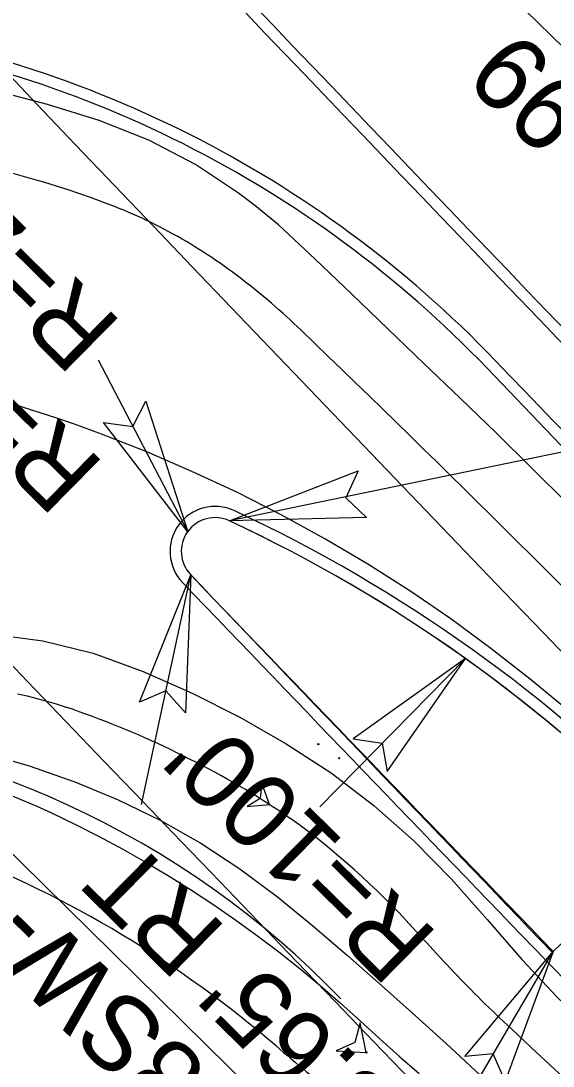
# Model space of a CAD drawing. Extents: x 1262642 to 1268358, y 767825 to 773481.
# Drawn here: x 1266795.4 to 1266830.8, y 772090.6 to 772160.2 of the extents above; entities that cross this region are included whole.
import ezdxf

# ---------------------------------------------------------------- set-up
doc = ezdxf.new("R2010")
doc.units = 0
for name, color, linetype in [('Prop Conc 5in Monolithic Keyed In Island', 7, 'Continuous'), ('Prop Dimension', 7, 'Continuous'), ('Prop Dimension Text', 7, 'Continuous'), ('Prop EOT', 7, 'Continuous'), ('Prop Horizontal Alignment', 7, 'Continuous'), ('Prop Lane Lines', 7, 'Continuous'), ('Prop Shade Light', 7, 'Continuous'), ('Prop Shade Medium', 7, 'Continuous'), ('Prop Terminator CELL', 7, 'Continuous'), ('Scratch_Level_3', 7, 'Continuous')]:
    doc.layers.add(name, color=color, linetype=linetype)

msp = doc.modelspace()

# ---------------------------------------------------------------- linework, layer by layer
at = {"layer": 'Prop Conc 5in Monolithic Keyed In Island'}
msp.add_line((1266830.753, 772098.262), (1266838.671, 772105.898), dxfattribs=at)
for centre, radius, start, end in [((1275047.307, 780021.225), 11385.75, 223.6505027, 224.2564693), ((1266772.773, 772085.698), 75, 43.80193, 82.74583), ((1275047.307, 780021.225), 11389.75, 223.8019285, 224.2564698), ((1266808.274, 772124.892), 2.25, 64.96498, 223.78327), ((1266767.185, 772036.948), 99.319, 43.95043, 64.95755), ((1275064.49, 780003.257), 11414.25, 223.6584765, 223.8330599)]:
    msp.add_arc(centre, radius, start, end, dxfattribs=at)
at = {"layer": 'Prop Dimension Text'}
for p, q in [((1266851.227, 772138.936), (1266824.646, 772165.127)), ((1266800.488, 772137.651), (1266806.45, 772126.196)), ((1266820.023, 772079.893), (1266772.475, 772126.743)), ((1266815.248, 772107.896), (1266824.925, 772117.759))]:
    msp.add_line(p, q, dxfattribs=at)
for points in [[(1266948.393, 772155.686), (1266809.22, 772126.931)], [(1266803.368, 772108.057), (1266806.649, 772123.335)], [(1266822.822, 772084.668), (1266830.753, 772098.262)]]:
    msp.add_lwpolyline(points, dxfattribs=at)
at = {"layer": 'Prop EOT'}
for centre, radius, start, end in [((1275047.307, 780021.225), 11385, 223.6505027, 224.2564693), ((1266772.773, 772085.698), 74.25, 43.80193, 82.74583), ((1275047.307, 780021.225), 11390.5, 223.8019285, 224.2564693), ((1266808.274, 772124.892), 3, 64.96497, 223.78327), ((1266767.226, 772037.005), 100, 43.95786, 64.96497), ((1275047.307, 780021.225), 11415, 223.7832702, 223.9578537), ((1275047.307, 780021.225), 11415, 223.9578709, 224.2520264), ((1266699.67, 771910.536), 200, 44.17518, 66.65746)]:
    msp.add_arc(centre, radius, start, end, dxfattribs=at)
at = {"layer": 'Prop Horizontal Alignment'}
msp.add_arc((1275047.307, 780021.225), 11400, 222.9935866, 225.4043192, dxfattribs=at)
at = {"layer": 'Prop Lane Lines'}
for centre, radius, start, end in [((1275047.307, 780021.225), 11427, 222.9935866, 225.3637298), ((1266773.416, 772053.492), 60, 43.9174, 86.78605)]:
    msp.add_arc(centre, radius, start, end, dxfattribs=at)
at = {"layer": 'Prop Shade Light'}
msp.add_arc((1266699.67, 771910.536), 200, 44.17518, 66.65746, dxfattribs=at)
at = {"layer": 'Prop Shade Medium'}
msp.add_line((1266830.753, 772098.262), (1266838.671, 772105.898), dxfattribs=at)
for centre, radius, start, end in [((1275047.307, 780021.225), 11385.75, 223.6505027, 224.2564693), ((1266772.773, 772085.698), 75, 43.80193, 82.74583), ((1275047.307, 780021.225), 11389.75, 223.8019285, 224.2564698), ((1266808.274, 772124.892), 2.25, 64.96498, 223.78327), ((1266767.226, 772037.005), 99.25, 43.95785, 64.96498), ((1275047.307, 780021.225), 11414.25, 223.7832702, 223.9578537)]:
    msp.add_arc(centre, radius, start, end, dxfattribs=at)
at = {"layer": 'Prop Terminator CELL'}
for points in [[(1266803.67, 772134.895), (1266806.45, 772126.196), (1266800.852, 772133.485), (1266802.803, 772133.204)], [(1266818.35, 772127.15), (1266809.22, 772126.931), (1266817.79, 772130.25), (1266816.971, 772128.458)], [(1266803.243, 772114.862), (1266806.649, 772123.335), (1266806.312, 772114.151), (1266804.989, 772115.612)], [(1266819.728, 772110.249), (1266824.925, 772117.759), (1266817.445, 772112.42), (1266819.392, 772112.12)], [(1266824.879, 772091.27), (1266830.753, 772098.262), (1266827.574, 772089.639), (1266826.772, 772091.439)]]:
    msp.add_lwpolyline(points, close=True, dxfattribs=at)
at = {"layer": 'Scratch_Level_3'}
for points in [[(1266810.921, 772147.927), (1266809.834, 772148.75), (1266806.958, 772150.648), (1266803.86, 772152.275), (1266800.55, 772153.584), (1266797.116, 772154.652), (1266793.633, 772155.548), (1266790.109, 772156.268), (1266786.554, 772156.812), (1266782.975, 772157.177), (1266779.383, 772157.363), (1266775.786, 772157.37), (1266772.199, 772157.207), (1266768.664, 772157.055), (1266765.183, 772157.013), (1266761.734, 772157.034), (1266758.285, 772156.973), (1266754.839, 772156.827), (1266751.398, 772156.596), (1266747.963, 772156.28), (1266747.277, 772156.207)], [(1266813.987, 772139.615), (1266813.747, 772139.845), (1266813.505, 772140.074), (1266813.261, 772140.302), (1266813.016, 772140.528), (1266812.769, 772140.752), (1266812.521, 772140.975), (1266812.271, 772141.195), (1266812.02, 772141.414), (1266811.767, 772141.631), (1266811.512, 772141.846), (1266811.256, 772142.059), (1266810.998, 772142.27), (1266810.738, 772142.48), (1266810.477, 772142.687), (1266810.214, 772142.892), (1266809.95, 772143.095), (1266809.684, 772143.295), (1266809.416, 772143.494), (1266809.147, 772143.69), (1266808.875, 772143.884), (1266808.603, 772144.075), (1266808.328, 772144.265), (1266808.052, 772144.451), (1266807.774, 772144.636), (1266807.495, 772144.817), (1266807.214, 772144.996), (1266806.931, 772145.173), (1266806.647, 772145.347), (1266806.361, 772145.518), (1266806.073, 772145.687), (1266805.784, 772145.852), (1266805.493, 772146.015), (1266805.2, 772146.175), (1266804.906, 772146.332), (1266804.611, 772146.486), (1266804.314, 772146.637), (1266804.015, 772146.785), (1266803.715, 772146.93), (1266803.413, 772147.071), (1266803.11, 772147.21), (1266802.805, 772147.345), (1266802.499, 772147.477), (1266802.191, 772147.605), (1266801.882, 772147.73), (1266801.572, 772147.852)], [(1266831.727, 772128.067), (1266829.359, 772130.423), (1266826.98, 772132.77), (1266824.574, 772135.088), (1266822.154, 772137.394), (1266819.755, 772139.72), (1266817.35, 772142.038), (1266814.937, 772144.349), (1266812.485, 772146.631), (1266810.921, 772147.927)], [(1266798.928, 772133.354), (1266797.743, 772133.766), (1266794.83, 772134.705), (1266791.981, 772135.521), (1266789.217, 772136.214), (1266786.485, 772136.802), (1266783.759, 772137.291), (1266781.042, 772137.682), (1266778.316, 772137.981), (1266775.562, 772138.192), (1266772.773, 772138.32), (1266769.983, 772138.369), (1266767.182, 772138.349), (1266764.317, 772138.266), (1266761.377, 772138.127), (1266758.385, 772137.943), (1266755.42, 772137.732), (1266752.487, 772137.495), (1266749.6, 772137.263), (1266746.721, 772137.048), (1266746.147, 772137.008)], [(1266855.985, 772090.429), (1266853.612, 772092.905), (1266851.235, 772095.375), (1266848.861, 772097.832), (1266846.477, 772100.28), (1266844.081, 772102.715), (1266841.664, 772105.129), (1266839.218, 772107.514), (1266836.735, 772109.86), (1266836.735, 772109.86), (1266834.28, 772112.094), (1266831.78, 772114.272), (1266829.227, 772116.387), (1266826.618, 772118.431), (1266823.947, 772120.395), (1266821.215, 772122.27), (1266818.421, 772124.053), (1266815.569, 772125.74), (1266812.665, 772127.332), (1266809.716, 772128.827), (1266806.732, 772130.222), (1266803.724, 772131.515), (1266800.714, 772132.701), (1266798.928, 772133.354)], [(1266791.47, 772119.581), (1266793.471, 772119.384), (1266796.813, 772118.932), (1266800.167, 772118.113), (1266803.488, 772116.893), (1266806.745, 772115.46), (1266809.921, 772113.856), (1266813.009, 772112.086), (1266815.998, 772110.154), (1266818.826, 772107.988), (1266821.493, 772105.617), (1266824.007, 772103.084), (1266826.363, 772100.399), (1266828.673, 772097.733), (1266831.034, 772095.229), (1266833.472, 772092.899), (1266833.96, 772092.435)], [(1266795.129, 772115.42), (1266795.454, 772115.347), (1266795.778, 772115.271), (1266796.102, 772115.192), (1266796.425, 772115.109), (1266796.747, 772115.022), (1266797.068, 772114.932), (1266797.388, 772114.839), (1266797.707, 772114.741), (1266798.024, 772114.64), (1266798.34, 772114.535)], [(1266747.4, 772113.137), (1266747.688, 772113.115), (1266750.626, 772112.883), (1266753.663, 772112.644), (1266756.789, 772112.42), (1266760.041, 772112.978), (1266763.352, 772113.461), (1266766.738, 772113.677), (1266770.18, 772113.584), (1266773.653, 772113.244), (1266777.12, 772112.806), (1266780.572, 772112.261), (1266784.006, 772111.611), (1266787.419, 772110.855), (1266790.804, 772109.995), (1266794.134, 772108.899), (1266796.418, 772107.926)], [(1266790.812, 772111.995), (1266792.752, 772111.527), (1266795.913, 772110.611), (1266798.935, 772109.551), (1266801.818, 772108.362), (1266804.617, 772107.004), (1266807.322, 772105.471), (1266809.924, 772103.769), (1266812.415, 772101.91), (1266814.776, 772099.976), (1266817.068, 772098.001), (1266819.34, 772096.002), (1266821.6, 772093.982), (1266823.906, 772091.884), (1266826.269, 772089.697), (1266828.666, 772087.44), (1266829.144, 772086.984)], [(1266796.418, 772107.926), (1266797.387, 772107.482), (1266798.987, 772106.713), (1266800.57, 772105.909), (1266802.135, 772105.069), (1266803.68, 772104.195), (1266805.206, 772103.286), (1266806.71, 772102.343), (1266808.194, 772101.366), (1266809.655, 772100.357), (1266811.093, 772099.315), (1266812.507, 772098.241), (1266813.897, 772097.135), (1266815.262, 772095.999), (1266816.601, 772094.833), (1266817.914, 772093.637), (1266819.221, 772092.445), (1266820.534, 772091.282), (1266821.854, 772090.145)], [(1266811.896, 772108.05), (1266812.178, 772107.871), (1266812.457, 772107.689), (1266812.733, 772107.503), (1266813.008, 772107.314), (1266813.28, 772107.121)], [(1266821.425, 772099.846), (1266821.649, 772099.6), (1266821.873, 772099.353), (1266822.098, 772099.107), (1266822.323, 772098.861), (1266822.548, 772098.615), (1266822.773, 772098.369), (1266822.999, 772098.124), (1266823.226, 772097.88), (1266823.453, 772097.636), (1266823.681, 772097.392), (1266823.909, 772097.15), (1266824.138, 772096.907), (1266824.368, 772096.666), (1266824.598, 772096.425), (1266824.83, 772096.185), (1266825.062, 772095.946), (1266825.295, 772095.708), (1266825.529, 772095.471), (1266825.765, 772095.234), (1266826.001, 772094.999), (1266826.238, 772094.765), (1266826.477, 772094.532), (1266826.716, 772094.301), (1266826.957, 772094.07), (1266827.2, 772093.842), (1266827.443, 772093.614)], [(1266812.324, 772091.98), (1266812.577, 772091.763), (1266812.83, 772091.546), (1266813.083, 772091.329), (1266813.337, 772091.113), (1266813.591, 772090.898), (1266813.846, 772090.683), (1266814.101, 772090.468), (1266814.357, 772090.254), (1266814.614, 772090.041), (1266814.87, 772089.829), (1266815.128, 772089.617), (1266815.386, 772089.406), (1266815.645, 772089.196), (1266815.904, 772088.987)]]:
    msp.add_lwpolyline(points, dxfattribs=at)
for points in [[(1266811.896, 772108.05), (1266811.381, 772109.459), (1266811.263, 772108.452), (1266810.402, 772107.917)], [(1266818.33, 772091.544), (1266817.922, 772093.502), (1266817.572, 772092.196), (1266816.334, 772091.656)]]:
    msp.add_lwpolyline(points, close=True, dxfattribs=at)
for centre in [(1266815.137, 772112.059), (1266815.137, 772112.059), (1266816.521, 772111.13), (1266816.521, 772111.13), (1266818.33, 772091.544), (1266818.33, 772091.544)]:
    msp.add_circle(centre, 0.0417, dxfattribs=at)
for centre, radius, start, end in [((1266777.458, 772085.377), 66.967, 68.89437, 91.22346), ((1266039.974, 771332.91), 1117.975, 44.120486, 46.184771), ((1266778.081, 772054.776), 63.1, 57.5953, 71.2725), ((1266782.244, 772064.178), 52.985, 42.31332, 54.14387), ((1266763.848, 772035.636), 74.328, 49.29252, 68.80212), ((1266573.771, 771819.313), 373.618, 41.00041, 47.23753)]:
    msp.add_arc(centre, radius, start, end, dxfattribs=at)

# ---------------------------------------------------------------- texts
at = {"layer": 'Prop Dimension'}
for s, p in [("R=2.25'", (1266802.18, 772140.047)), ("R=2.25'", (1266801.019, 772130.645)), ("R=100'", (1266823.204, 772099.353))]:
    msp.add_text(s, height=5, rotation=135.42387, dxfattribs=at).set_placement(p)
at = {"layer": 'Prop Dimension Text'}
for s, p in [('-L- +81.99', (1266850.152, 772138.268)), ('-Y38SW- +95.38', (1266815.384, 772083.074)), ("3.65' RT", (1266820.648, 772088.416))]:
    msp.add_text(s, height=5, rotation=135.42387, dxfattribs=at).set_placement(p)

doc.saveas('drawing.dxf')
